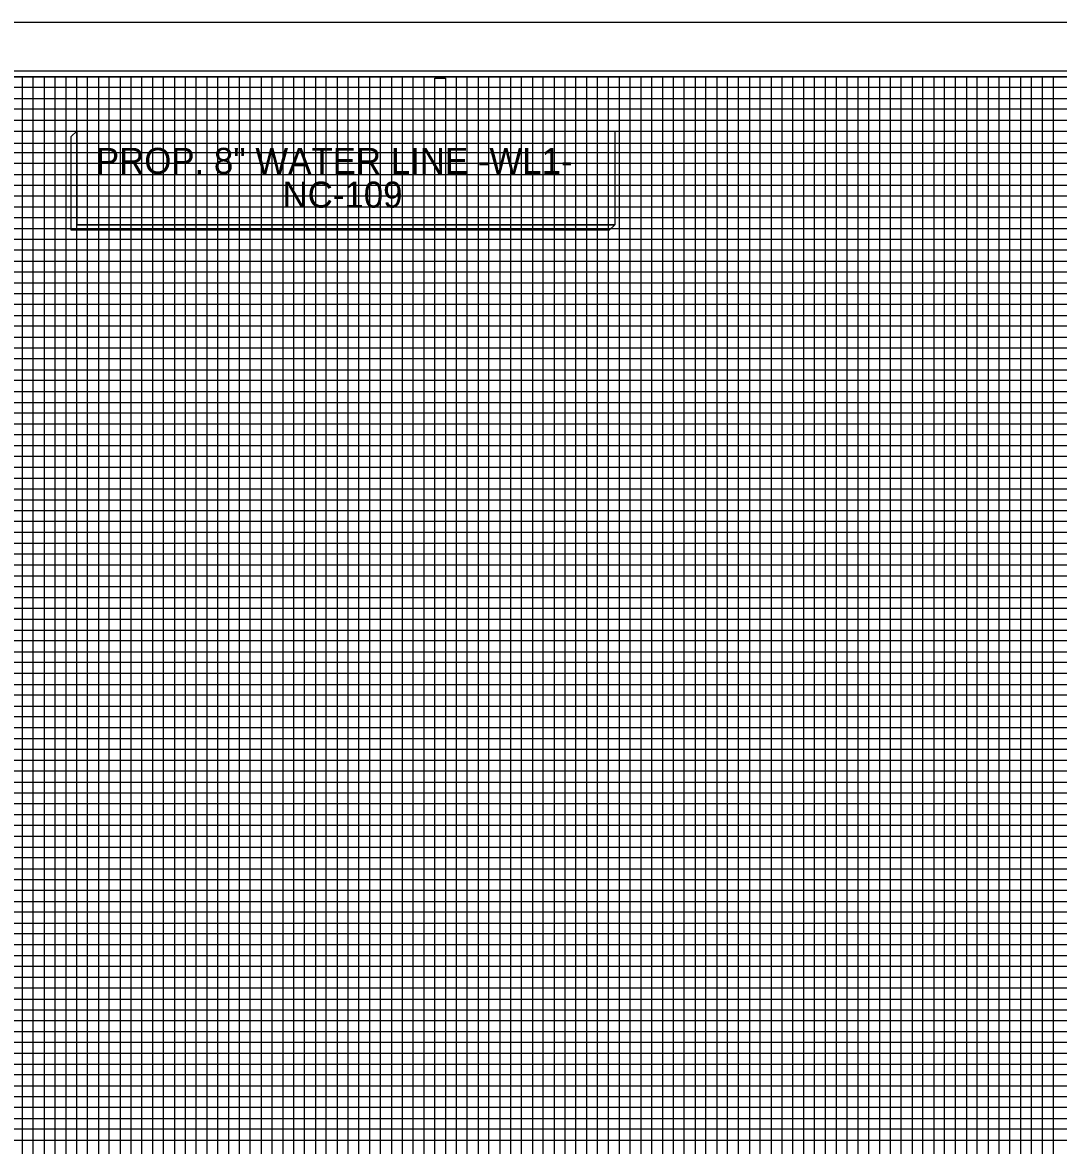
# Model space of a CAD drawing. Extents: x 3814791 to 3815465, y 1224203 to 1224643.
# Drawn here: x 3815088.1 to 3815279.1, y 1224436.2 to 1224643.2 of the extents above; entities that cross this region are included whole.
import ezdxf

# ---------------------------------------------------------------- set-up
doc = ezdxf.new("R2010")
doc.units = 0
for name, color, linetype in [('COGO Default Chain', 7, 'Continuous'), ('Exist Roads EOP', 7, 'Continuous'), ('Pattern 49', 7, 'Continuous'), ('Scratch_Level_1', 7, 'Continuous')]:
    doc.layers.add(name, color=color, linetype=linetype)

msp = doc.modelspace()

# ---------------------------------------------------------------- linework, layer by layer
at = {"layer": 'COGO Default Chain'}
for p, q in [((3815097.11, 1224622.19), (3815098.11, 1224623.19)), ((3815197.29, 1224605.91), (3815196.29, 1224604.91)), ((3815197.29, 1224605.91), (3815196.29, 1224604.91))]:
    msp.add_line(p, q, dxfattribs=at)
msp.add_lwpolyline([(3815098.11, 1224623.19), (3815197.29, 1224623.19), (3815197.29, 1224605.91), (3815098.11, 1224605.91)], close=True, dxfattribs=at)
for points in [[(3815098.11, 1224623.19), (3815098.11, 1224605.91), (3815197.29, 1224605.91)], [(3815196.29, 1224604.91), (3815097.11, 1224604.91), (3815097.11, 1224622.19)]]:
    msp.add_lwpolyline(points, dxfattribs=at)
at = {"layer": 'Exist Roads EOP'}
for p, q in [((3814878.11, 1224633.21), (3815378.11, 1224633.21)), ((3815438.11, 1224561.21), (3814878.11, 1224561.21)), ((3814878.11, 1224559.21), (3815438.11, 1224559.21)), ((3815438.11, 1224551.21), (3814878.11, 1224551.21))]:
    msp.add_line(p, q, dxfattribs=at)
for points in [[(3815458.11, 1224633.21), (3814858.11, 1224633.21), (3814858.11, 1224213.21), (3815458.11, 1224213.21)], [(3814878.11, 1224633.21), (3814878.11, 1224223.21), (3815438.11, 1224223.21), (3815438.11, 1224578.19), (3815378.11, 1224578.19), (3815378.11, 1224633.21)]]:
    msp.add_lwpolyline(points, close=True, dxfattribs=at)
for points in [[(3815088.11, 1224223.21), (3815088.11, 1224633.21), (3815108.11, 1224633.21), (3815108.11, 1224223.21)], [(3815090.11, 1224223.21), (3815090.11, 1224633.21), (3815092.11, 1224633.21), (3815092.11, 1224223.21)], [(3815094.11, 1224223.21), (3815094.11, 1224633.21), (3815096.11, 1224633.21), (3815096.11, 1224223.21)], [(3815098.11, 1224223.21), (3815098.11, 1224633.21), (3815118.11, 1224633.21), (3815118.11, 1224223.21)], [(3815100.11, 1224223.21), (3815100.11, 1224633.21), (3815102.11, 1224633.21), (3815102.11, 1224223.21)], [(3815104.11, 1224223.21), (3815104.11, 1224633.21), (3815106.11, 1224633.21), (3815106.11, 1224223.21)], [(3815110.11, 1224223.21), (3815110.11, 1224633.21), (3815112.11, 1224633.21), (3815112.11, 1224223.21)], [(3815114.11, 1224223.21), (3815114.11, 1224633.21), (3815116.11, 1224633.21), (3815116.11, 1224223.21)], [(3815120.11, 1224223.21), (3815120.11, 1224633.21), (3815122.11, 1224633.21), (3815122.11, 1224223.21)], [(3815124.11, 1224223.21), (3815124.11, 1224633.21), (3815126.11, 1224633.21), (3815126.11, 1224223.21)], [(3815128.11, 1224223.21), (3815128.11, 1224633.21), (3815148.11, 1224633.21), (3815148.11, 1224223.21)], [(3815130.11, 1224223.21), (3815130.11, 1224633.21), (3815132.11, 1224633.21), (3815132.11, 1224223.21)], [(3815134.11, 1224223.21), (3815134.11, 1224633.21), (3815136.11, 1224633.21), (3815136.11, 1224223.21)], [(3815138.11, 1224223.21), (3815138.11, 1224633.21), (3815158.11, 1224633.21), (3815158.11, 1224223.21)], [(3815140.11, 1224223.21), (3815140.11, 1224633.21), (3815142.11, 1224633.21), (3815142.11, 1224223.21)], [(3815144.11, 1224223.21), (3815144.11, 1224633.21), (3815146.11, 1224633.21), (3815146.11, 1224223.21)], [(3815150.11, 1224223.21), (3815150.11, 1224633.21), (3815152.11, 1224633.21), (3815152.11, 1224223.21)], [(3815154.11, 1224223.21), (3815154.11, 1224633.21), (3815156.11, 1224633.21), (3815156.11, 1224223.21)], [(3815160.11, 1224223.21), (3815160.11, 1224633.21), (3815162.11, 1224633.21), (3815162.11, 1224223.21)], [(3815164.11, 1224223.21), (3815164.11, 1224632.97), (3815166.11, 1224632.97), (3815166.11, 1224223.21)], [(3815168.11, 1224223.21), (3815168.11, 1224633.21), (3815188.11, 1224633.21), (3815188.11, 1224223.21)], [(3815170.11, 1224223.21), (3815170.11, 1224633.21), (3815172.11, 1224633.21), (3815172.11, 1224223.21)], [(3815174.11, 1224223.21), (3815174.11, 1224633.21), (3815176.11, 1224633.21), (3815176.11, 1224223.21)], [(3815178.11, 1224223.21), (3815178.11, 1224633.21), (3815198.11, 1224633.21), (3815198.11, 1224223.21)], [(3815180.11, 1224223.21), (3815180.11, 1224633.21), (3815182.11, 1224633.21), (3815182.11, 1224223.21)], [(3815184.11, 1224223.21), (3815184.11, 1224633.21), (3815186.11, 1224633.21), (3815186.11, 1224223.21)], [(3815190.11, 1224223.21), (3815190.11, 1224633.21), (3815192.11, 1224633.21), (3815192.11, 1224223.21)], [(3815194.11, 1224223.21), (3815194.11, 1224633.21), (3815196.11, 1224633.21), (3815196.11, 1224223.21)], [(3815200.11, 1224223.21), (3815200.11, 1224633.21), (3815202.11, 1224633.21), (3815202.11, 1224223.21)], [(3815204.11, 1224223.21), (3815204.11, 1224633.21), (3815206.11, 1224633.21), (3815206.11, 1224223.21)], [(3815208.11, 1224223.21), (3815208.11, 1224633.21), (3815228.11, 1224633.21), (3815228.11, 1224223.21)], [(3815210.11, 1224223.21), (3815210.11, 1224633.21), (3815212.11, 1224633.21), (3815212.11, 1224223.21)], [(3815214.11, 1224223.21), (3815214.11, 1224633.21), (3815216.11, 1224633.21), (3815216.11, 1224223.21)], [(3815218.11, 1224223.21), (3815218.11, 1224633.21), (3815238.11, 1224633.21), (3815238.11, 1224223.21)], [(3815220.11, 1224223.21), (3815220.11, 1224633.21), (3815222.11, 1224633.21), (3815222.11, 1224223.21)], [(3815224.11, 1224223.21), (3815224.11, 1224633.21), (3815226.11, 1224633.21), (3815226.11, 1224223.21)], [(3815230.11, 1224223.21), (3815230.11, 1224633.21), (3815232.11, 1224633.21), (3815232.11, 1224223.21)], [(3815234.11, 1224223.21), (3815234.11, 1224633.21), (3815236.11, 1224633.21), (3815236.11, 1224223.21)], [(3815240.11, 1224223.21), (3815240.11, 1224633.21), (3815242.11, 1224633.21), (3815242.11, 1224223.21)], [(3815244.11, 1224223.21), (3815244.11, 1224633.21), (3815246.11, 1224633.21), (3815246.11, 1224223.21)], [(3815248.11, 1224223.21), (3815248.11, 1224633.21), (3815268.11, 1224633.21), (3815268.11, 1224223.21)], [(3815250.11, 1224223.21), (3815250.11, 1224633.21), (3815252.11, 1224633.21), (3815252.11, 1224223.21)], [(3815254.11, 1224223.21), (3815254.11, 1224633.21), (3815256.11, 1224633.21), (3815256.11, 1224223.21)], [(3815258.11, 1224223.21), (3815258.11, 1224633.21), (3815278.11, 1224633.21), (3815278.11, 1224223.21)], [(3815260.11, 1224223.21), (3815260.11, 1224633.21), (3815262.11, 1224633.21), (3815262.11, 1224223.21)], [(3815264.11, 1224223.21), (3815264.11, 1224633.21), (3815266.11, 1224633.21), (3815266.11, 1224223.21)], [(3815270.11, 1224223.21), (3815270.11, 1224633.21), (3815272.11, 1224633.21), (3815272.11, 1224223.21)], [(3815274.11, 1224223.21), (3815274.11, 1224633.21), (3815276.11, 1224633.21), (3815276.11, 1224223.21)], [(3815378.09, 1224631.21), (3814878.11, 1224631.21), (3814878.11, 1224629.21), (3815378.09, 1224629.21)], [(3815378.09, 1224627.21), (3814878.11, 1224627.21), (3814878.11, 1224625.21), (3815378.09, 1224625.21)], [(3815378.09, 1224603.21), (3814858.15, 1224603.21), (3814858.15, 1224623.19), (3815378.09, 1224623.19)], [(3815378.09, 1224620.91), (3814878.11, 1224620.91), (3814878.11, 1224619.21), (3815378.09, 1224619.21)], [(3815378.09, 1224617.21), (3814878.11, 1224617.21), (3814878.11, 1224615.21), (3815378.09, 1224615.21)], [(3814858.11, 1224613.21), (3815378.09, 1224613.21)], [(3815378.09, 1224611.21), (3814878.11, 1224611.21), (3814878.11, 1224609.21), (3815378.09, 1224609.21)], [(3815378.11, 1224607.21), (3814878.11, 1224607.21), (3814878.11, 1224605.21), (3815378.09, 1224605.21)], [(3815378.09, 1224601.21), (3814878.11, 1224601.21), (3814878.11, 1224599.21), (3815378.09, 1224599.21)], [(3815378.09, 1224597.21), (3814878.11, 1224597.21), (3814878.11, 1224595.21), (3815378.09, 1224595.21)], [(3815378.09, 1224593.21), (3814858.11, 1224593.21), (3814858.11, 1224573.19), (3815458.11, 1224573.19)], [(3815378.09, 1224591.21), (3814878.11, 1224591.21), (3814878.11, 1224589.21), (3815378.09, 1224589.21)], [(3815378.09, 1224587.21), (3814878.11, 1224587.21), (3814878.11, 1224585.21), (3815378.09, 1224585.21)], [(3815458.11, 1224563.21), (3814858.11, 1224563.21), (3814858.11, 1224583.21), (3815378.09, 1224583.21)], [(3815378.09, 1224581.21), (3814878.11, 1224581.21), (3814878.11, 1224579.21), (3815378.09, 1224579.21)], [(3815438.11, 1224577.21), (3814878.11, 1224577.21), (3814878.11, 1224577.21), (3814878.11, 1224569.21), (3815438.11, 1224569.21)], [(3815438.11, 1224577.21), (3814878.11, 1224577.21), (3814878.11, 1224577.21), (3814878.11, 1224569.21), (3815458.11, 1224569.21)], [(3814878.11, 1224575.21), (3815438.11, 1224575.21)], [(3815438.11, 1224571.21), (3814878.11, 1224571.21)], [(3815438.11, 1224567.21), (3814878.11, 1224567.21), (3814878.11, 1224565.21), (3815438.11, 1224565.21)], [(3815438.11, 1224557.21), (3814878.11, 1224557.21), (3814878.11, 1224555.21), (3815438.11, 1224555.21)], [(3815458.11, 1224553.21), (3814858.11, 1224553.21), (3814858.11, 1224533.21), (3815458.11, 1224533.21)], [(3815438.11, 1224549.21), (3814878.11, 1224549.21), (3814878.11, 1224547.21), (3815438.11, 1224547.21)], [(3815438.11, 1224545.21), (3814878.11, 1224545.21)], [(3815458.11, 1224523.21), (3814858.11, 1224523.21), (3814858.11, 1224543.21), (3815458.11, 1224543.21)], [(3814878.11, 1224541.21), (3815438.11, 1224541.21)], [(3815438.11, 1224539.21), (3814878.11, 1224539.21), (3814878.11, 1224537.21), (3815438.11, 1224537.21)], [(3815438.11, 1224535.21), (3814878.11, 1224535.21), (3814878.11, 1224531.21), (3815438.11, 1224531.21)], [(3815438.11, 1224529.21), (3814878.11, 1224529.21), (3814878.11, 1224527.21), (3815438.11, 1224527.21)], [(3815438.11, 1224525.21), (3814878.11, 1224525.21), (3814878.11, 1224521.21), (3815438.11, 1224521.21)], [(3815438.11, 1224519.21), (3814878.11, 1224519.21), (3814878.11, 1224517.21), (3815438.11, 1224517.21)], [(3815438.11, 1224515.21), (3814878.11, 1224515.21), (3814878.11, 1224511.21), (3815438.11, 1224511.21)], [(3815458.11, 1224513.21), (3814858.11, 1224513.21), (3814858.11, 1224493.21), (3815458.11, 1224493.21)], [(3815438.11, 1224509.21), (3814878.11, 1224509.21), (3814878.11, 1224507.21), (3815438.11, 1224507.21)], [(3815438.11, 1224505.21), (3814878.11, 1224505.21), (3814878.11, 1224501.21), (3815438.11, 1224501.21)], [(3815458.11, 1224483.21), (3814858.11, 1224483.21), (3814858.11, 1224503.21), (3815458.11, 1224503.21)], [(3815438.11, 1224499.21), (3814878.11, 1224499.21), (3814878.11, 1224497.21), (3815438.11, 1224497.21)], [(3815438.11, 1224495.21), (3814878.11, 1224495.21), (3814878.11, 1224491.21), (3815438.11, 1224491.21)], [(3815438.11, 1224489.21), (3814878.11, 1224489.21), (3814878.11, 1224487.21), (3815438.11, 1224487.21)], [(3815438.11, 1224485.21), (3814878.11, 1224485.21), (3814878.11, 1224481.21), (3815438.11, 1224481.21)], [(3815438.11, 1224479.21), (3814878.11, 1224479.21), (3814878.11, 1224477.21), (3815438.11, 1224477.21)], [(3815438.11, 1224475.21), (3814878.11, 1224475.21), (3814878.11, 1224471.21), (3815438.11, 1224471.21)], [(3815458.11, 1224473.21), (3814858.11, 1224473.21), (3814858.11, 1224453.21), (3815458.11, 1224453.21)], [(3815438.11, 1224469.21), (3814878.11, 1224469.21), (3814878.11, 1224467.21), (3815438.11, 1224467.21)], [(3815438.11, 1224465.21), (3814878.11, 1224465.21), (3814878.11, 1224461.21), (3815438.11, 1224461.21)], [(3815458.11, 1224443.21), (3814858.11, 1224443.21), (3814858.11, 1224463.21), (3815458.11, 1224463.21)], [(3815438.11, 1224459.21), (3814878.11, 1224459.21), (3814878.11, 1224457.21), (3815438.11, 1224457.21)], [(3815438.11, 1224455.21), (3814878.11, 1224455.21), (3814878.11, 1224451.21), (3815438.11, 1224451.21)], [(3815438.11, 1224449.21), (3814878.11, 1224449.21), (3814878.11, 1224447.21), (3815438.11, 1224447.21)], [(3815438.11, 1224445.21), (3814878.11, 1224445.21), (3814878.11, 1224441.21), (3815438.11, 1224441.21)], [(3815438.11, 1224439.21), (3814878.11, 1224439.21), (3814878.11, 1224437.21), (3815438.11, 1224437.21)]]:
    msp.add_lwpolyline(points, dxfattribs=at)
at = {"layer": 'Pattern 49'}
msp.add_lwpolyline([(3815463.11, 1224634.23), (3814796.51, 1224634.23), (3814796.51, 1224212.19), (3815463.11, 1224212.19)], close=True, dxfattribs=at)
at = {"layer": 'Scratch_Level_1'}
msp.add_lwpolyline([(3815464.91, 1224643.21), (3814791.31, 1224643.21), (3814791.31, 1224203.21), (3815464.91, 1224203.21)], close=True, dxfattribs=at)

# ---------------------------------------------------------------- texts
at = {"layer": 'COGO Default Chain'}
for s, p in [('PROP. 8" WATER LINE -WL1-', (3815101.65, 1224615.29)), ('NC-109', (3815136.05, 1224609.07))]:
    msp.add_text(s, height=4.8, rotation=360, dxfattribs=at).set_placement(p)

doc.saveas('drawing.dxf')
